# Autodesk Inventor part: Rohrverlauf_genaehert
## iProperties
Created: 2007-07
Part Number: Rohrverlauf_genaehert
Document SubType Name: Modeling
Designer: krieg
Querschnitt: 122,718
Mass1: 482.90873180883636
Author: krieg
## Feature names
1. Sweeping1
